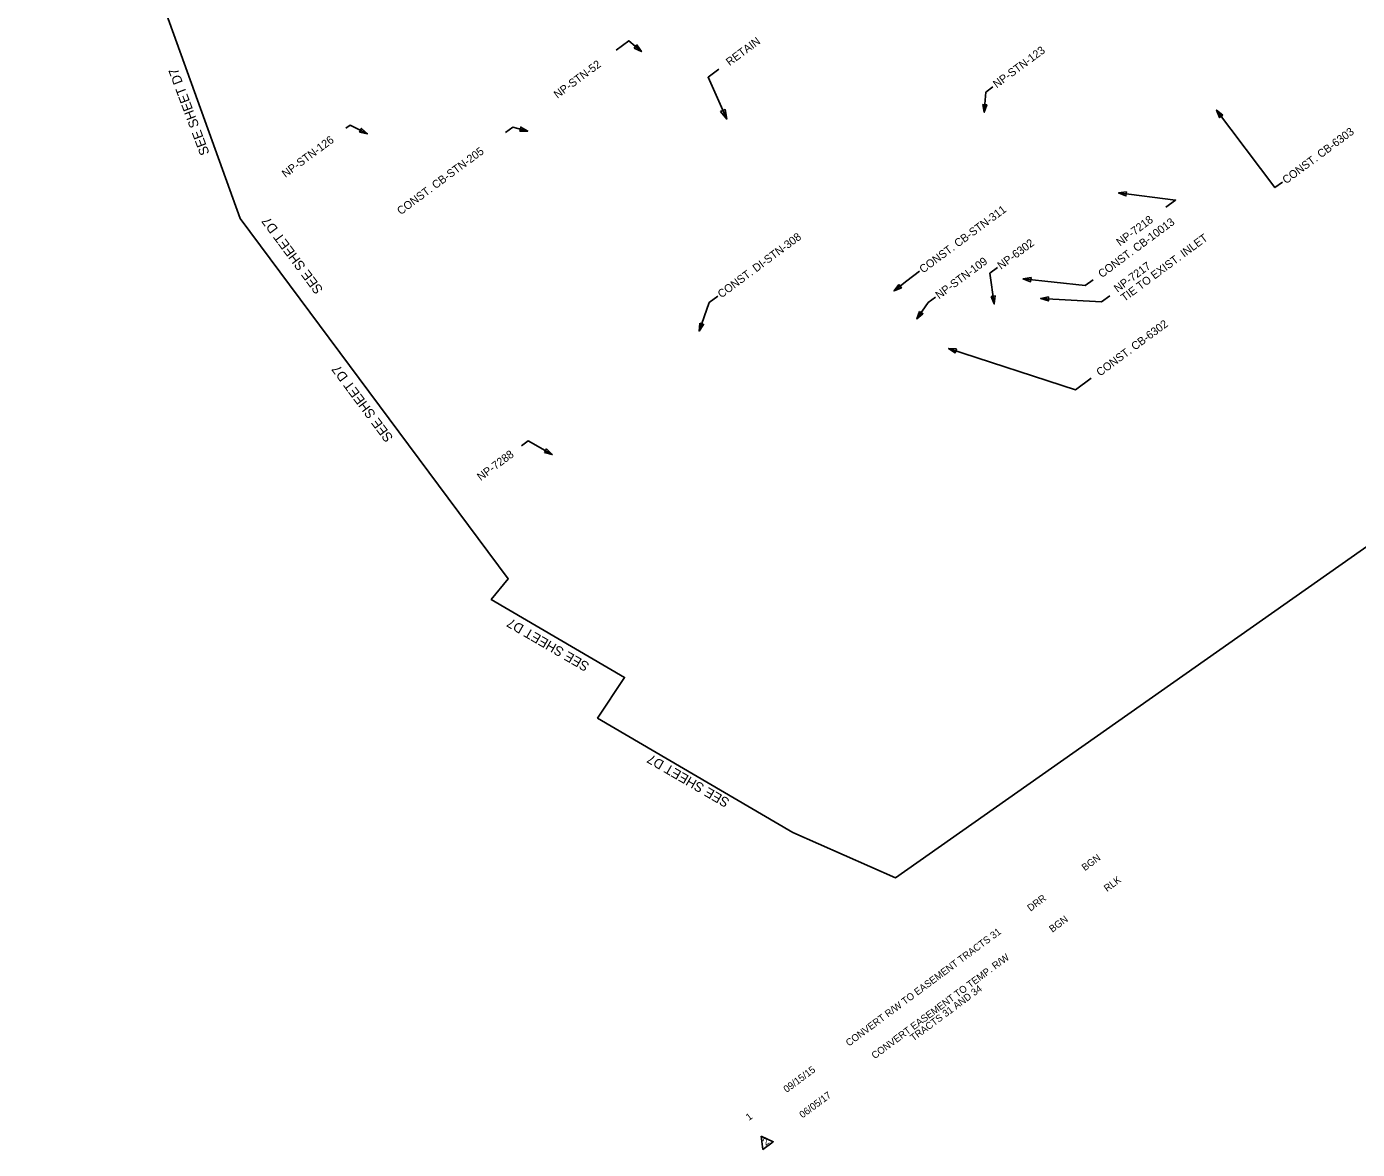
# Model space of a CAD drawing. Extents: x 1611197 to 1612945, y 1093889 to 1095652.
# Drawn here: x 1611197 to 1612028, y 1093889 to 1094591 of the extents above; entities that cross this region are included whole.
import ezdxf

# ---------------------------------------------------------------- set-up
doc = ezdxf.new("R2010")
doc.units = 0
for name, color, linetype in [('Plan_Clip', 7, 'Continuous'), ('RD_SHT_MatchLine', 7, 'Continuous'), ('RD_SHT_TX', 7, 'Continuous'), ('RD_TX_Drainage', 7, 'Continuous')]:
    doc.layers.add(name, color=color, linetype=linetype)

msp = doc.modelspace()

# ---------------------------------------------------------------- linework, layer by layer
at = {"layer": 'Plan_Clip'}
msp.add_lwpolyline([(1611268.69, 1094642.22), (1611330.47, 1094471.1), (1611497.89, 1094245.88), (1611487.26, 1094233.09), (1611570.53, 1094184.4), (1611553.65, 1094158.93), (1611675.76, 1094087.45), (1611739.82, 1094059.22), (1612815.43, 1094815.5), (1612742.51, 1095078.69), (1612653.41, 1095198.54), (1612656.92, 1095201.15), (1612580.15, 1095304.29), (1612588.44, 1095320.1), (1612485.6, 1095458.44), (1612364.08, 1095621.93), (1612226.86, 1095519.93), (1612207.59, 1095545.84), (1611204.37, 1094800.09), (1611196.97, 1094674.76)], close=True, dxfattribs=at)
msp.add_lwpolyline([(1611268.69, 1094642.22), (1611330.47, 1094471.1), (1611497.89, 1094245.88), (1611487.26, 1094233.09), (1611570.53, 1094184.4), (1611553.65, 1094158.93), (1611675.76, 1094087.45), (1611739.82, 1094059.22), (1612815.43, 1094815.5), (1612742.51, 1095078.69), (1612653.41, 1095198.54), (1612656.92, 1095201.15), (1612580.15, 1095304.29), (1612588.44, 1095320.1), (1612485.6, 1095458.44), (1612364.08, 1095621.93), (1612226.86, 1095519.93), (1612207.59, 1095545.84), (1611204.37, 1094800.09), (1611196.97, 1094674.76)], close=True, dxfattribs=at)
msp.add_lwpolyline([(1611268.69, 1094642.22), (1611330.47, 1094471.1), (1611497.89, 1094245.88), (1611487.26, 1094233.09), (1611570.53, 1094184.4), (1611553.65, 1094158.93), (1611675.76, 1094087.45), (1611739.82, 1094059.22), (1612815.43, 1094815.5), (1612742.51, 1095078.69), (1612653.41, 1095198.54), (1612656.92, 1095201.15), (1612580.15, 1095304.29), (1612588.44, 1095320.1), (1612485.6, 1095458.44), (1612364.08, 1095621.93), (1612226.86, 1095519.93), (1612207.59, 1095545.84), (1611204.37, 1094800.09), (1611196.97, 1094674.76)], close=True, dxfattribs=at)
msp.add_lwpolyline([(1611268.69, 1094642.22), (1611330.47, 1094471.1), (1611497.89, 1094245.88), (1611487.26, 1094233.09), (1611570.53, 1094184.4), (1611553.65, 1094158.93), (1611675.76, 1094087.45), (1611739.82, 1094059.22), (1612815.43, 1094815.5), (1612742.51, 1095078.69), (1612653.41, 1095198.54), (1612656.92, 1095201.15), (1612580.15, 1095304.29), (1612588.44, 1095320.1), (1612485.6, 1095458.44), (1612364.08, 1095621.93), (1612226.86, 1095519.93), (1612207.59, 1095545.84), (1611204.37, 1094800.09), (1611196.97, 1094674.76)], close=True, dxfattribs=at)
msp.add_lwpolyline([(1611268.69, 1094642.22), (1611330.47, 1094471.1), (1611497.89, 1094245.88), (1611487.26, 1094233.09), (1611570.53, 1094184.4), (1611553.65, 1094158.93), (1611675.76, 1094087.45), (1611739.82, 1094059.22), (1612815.43, 1094815.5), (1612742.51, 1095078.69), (1612653.41, 1095198.54), (1612656.92, 1095201.15), (1612580.15, 1095304.29), (1612588.44, 1095320.1), (1612485.6, 1095458.44), (1612364.08, 1095621.93), (1612226.86, 1095519.93), (1612207.59, 1095545.84), (1611204.37, 1094800.09), (1611196.97, 1094674.76)], close=True, dxfattribs=at)
msp.add_lwpolyline([(1611268.69, 1094642.22), (1611330.47, 1094471.1), (1611497.89, 1094245.88), (1611487.26, 1094233.09), (1611570.53, 1094184.4), (1611553.65, 1094158.93), (1611675.76, 1094087.45), (1611739.82, 1094059.22), (1612815.43, 1094815.5), (1612742.51, 1095078.69), (1612653.41, 1095198.54), (1612656.92, 1095201.15), (1612580.15, 1095304.29), (1612588.44, 1095320.1), (1612485.6, 1095458.44), (1612364.08, 1095621.93), (1612226.86, 1095519.93), (1612207.59, 1095545.84), (1611204.37, 1094800.09), (1611196.97, 1094674.76)], close=True, dxfattribs=at)
msp.add_lwpolyline([(1611268.69, 1094642.22), (1611330.47, 1094471.1), (1611497.89, 1094245.88), (1611487.26, 1094233.09), (1611570.53, 1094184.4), (1611553.65, 1094158.93), (1611675.76, 1094087.45), (1611739.82, 1094059.22), (1612815.43, 1094815.5), (1612742.51, 1095078.69), (1612653.41, 1095198.54), (1612656.92, 1095201.15), (1612580.15, 1095304.29), (1612588.44, 1095320.1), (1612485.6, 1095458.44), (1612364.08, 1095621.93), (1612226.86, 1095519.93), (1612207.59, 1095545.84), (1611204.37, 1094800.09), (1611196.97, 1094674.76)], close=True, dxfattribs=at)
msp.add_lwpolyline([(1611268.69, 1094642.22), (1611330.47, 1094471.1), (1611497.89, 1094245.88), (1611487.26, 1094233.09), (1611570.53, 1094184.4), (1611553.65, 1094158.93), (1611675.76, 1094087.45), (1611739.82, 1094059.22), (1612815.43, 1094815.5), (1612742.51, 1095078.69), (1612653.41, 1095198.54), (1612656.92, 1095201.15), (1612580.15, 1095304.29), (1612588.44, 1095320.1), (1612485.6, 1095458.44), (1612364.08, 1095621.93), (1612226.86, 1095519.93), (1612207.59, 1095545.84), (1611204.37, 1094800.09), (1611196.97, 1094674.76)], close=True, dxfattribs=at)
at = {"layer": 'RD_SHT_TX'}
msp.add_lwpolyline([(1611655.87, 1093897.72), (1611656.96, 1093889.47), (1611663.45, 1093894.29)], close=True, dxfattribs=at)
at = {"layer": 'RD_TX_Drainage'}
for points in [[(1611565.34, 1094576.19), (1611573.27, 1094582.09), (1611581.09, 1094575.38)], [(1611629.54, 1094564.34), (1611622.75, 1094559.29), (1611634.36, 1094533.18)], [(1611800.71, 1094553.3), (1611796.16, 1094549.92), (1611795.23, 1094537.4)], [(1611981.55, 1094493.83), (1611976.92, 1094490.38), (1611940.46, 1094538.79)], [(1611396.41, 1094527.45), (1611399.07, 1094529.42), (1611409.85, 1094524.06)], [(1611496.07, 1094524.79), (1611500.69, 1094528.22), (1611510.03, 1094525.72)], [(1611908.81, 1094478.06), (1611914.86, 1094482.55), (1611879.18, 1094487.03)], [(1611754.76, 1094438.07), (1611746.8, 1094432.15), (1611738.96, 1094425.78)], [(1611803.47, 1094440.41), (1611798.76, 1094436.9), (1611801.53, 1094417.71)], [(1611863.26, 1094432.77), (1611858.36, 1094429.12), (1611819.58, 1094433.35)], [(1611628.75, 1094422.54), (1611623.43, 1094418.58), (1611617.15, 1094400.75)], [(1611764.77, 1094421.91), (1611760.22, 1094418.53), (1611753.19, 1094408.31)], [(1611873.75, 1094422.79), (1611868.6, 1094418.97), (1611830.6, 1094421.17)], [(1611862.12, 1094371.27), (1611852.33, 1094364), (1611772.99, 1094389.88)], [(1611506.22, 1094329.08), (1611510.29, 1094332.1), (1611525.38, 1094323.62)]]:
    msp.add_lwpolyline(points, dxfattribs=at)
for points in [[(1611576.58, 1094577.55), (1611581.09, 1094575.38), (1611578.27, 1094579.51)], [(1611794.3, 1094542.31), (1611795.23, 1094537.4), (1611796.88, 1094542.12)], [(1611630.58, 1094537.84), (1611634.36, 1094533.18), (1611633.42, 1094539.1)], [(1611944.4, 1094535.71), (1611940.46, 1094538.79), (1611942.33, 1094534.16)], [(1611404.95, 1094525.05), (1611409.85, 1094524.06), (1611406.1, 1094527.37)], [(1611505.03, 1094525.72), (1611510.03, 1094525.72), (1611505.7, 1094528.22)], [(1611884.13, 1094487.71), (1611879.18, 1094487.03), (1611883.81, 1094485.14)], [(1611824.52, 1094434.11), (1611819.58, 1094433.35), (1611824.24, 1094431.54)], [(1611741.89, 1094429.83), (1611738.96, 1094425.78), (1611743.52, 1094427.82)], [(1611799.56, 1094422.3), (1611801.53, 1094417.71), (1611802.12, 1094422.67)], [(1611835.5, 1094422.18), (1611830.6, 1094421.17), (1611835.35, 1094419.6)], [(1611754.86, 1094413.02), (1611753.19, 1094408.31), (1611756.99, 1094411.55)], [(1611617.53, 1094405.74), (1611617.15, 1094400.75), (1611619.97, 1094404.88)], [(1611777.98, 1094389.62), (1611772.99, 1094389.88), (1611777.18, 1094387.16)], [(1611520.54, 1094324.86), (1611525.38, 1094323.62), (1611521.81, 1094327.11)]]:
    msp.add_lwpolyline(points, close=True, dxfattribs=at)

# ---------------------------------------------------------------- texts
at = {"layer": 'RD_SHT_MatchLine'}
for rotation, p in [(110.63846, (1611311.32, 1094511.88)), (126.62559, (1611382.5, 1094426.67)), (126.67686, (1611426.29, 1094334.16)), (149.9156, (1611549.07, 1094192.88)), (149.9156, (1611636.67, 1094107.95))]:
    msp.add_text('SEE SHEET D7', height=6, rotation=rotation, dxfattribs=at).set_placement(p)
at = {"layer": 'RD_SHT_TX'}
for s, p in [('BGN', (1611858.18, 1094063.22)), ('RLK', (1611872.01, 1094050.2)), ('DRR', (1611824.17, 1094037.94)), ('BGN', (1611837.82, 1094024.78)), ('CONVERT R/W TO EASEMENT TRACTS 31', (1611710.76, 1093953.64)), ('CONVERT EASEMENT TO TEMP. R/W', (1611726.86, 1093945.73)), ('TRACTS 31 AND 34', (1611751.02, 1093956.83)), ('09/15/15', (1611671.83, 1093924.7)), ('06/05/17', (1611681.74, 1093908.76)), ('1', (1611648.29, 1093907.19)), ('2', (1611658.76, 1093891.68))]:
    msp.add_text(s, height=4.4, rotation=36.62559, dxfattribs=at).set_placement(p)
at = {"layer": 'RD_TX_Drainage'}
for s, rotation, p in [('RETAIN', 36.62559, (1611636.21, 1094566.19)), ('NP-STN-123', 36.62397, (1611803.06, 1094552.31)), ('NP-STN-52', 36.62397, (1611528.63, 1094545.79)), ('CONST. CB-6303', 36.62397, (1611983.85, 1094492.42)), ('NP-STN-126', 36.62397, (1611358.74, 1094496.33)), ('CONST. CB-STN-205', 36.62397, (1611430.72, 1094473.1)), ('CONST. CB-STN-311', 36.62397, (1611757.06, 1094436.66)), ('CONST. CB-10013', 36.62397, (1611868.77, 1094433.74)), ('NP-7218', 36.62397, (1611880.07, 1094453.57)), ('CONST. DI-STN-308', 36.62397, (1611631.05, 1094421.13)), ('TIE TO EXIST. INLET', 36.62397, (1611882.89, 1094418.87)), ('NP-6302', 36.62397, (1611805.77, 1094439)), ('NP-STN-109', 36.62397, (1611767.06, 1094420.5)), ('NP-7217', 36.62397, (1611878.59, 1094424.65)), ('CONST. CB-6302', 36.62397, (1611867.62, 1094372.25)), ('NP-7288', 36.62559, (1611480.69, 1094306.98))]:
    msp.add_text(s, height=5, rotation=rotation, dxfattribs=at).set_placement(p)

doc.saveas('drawing.dxf')
